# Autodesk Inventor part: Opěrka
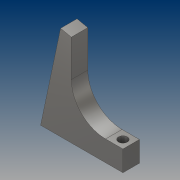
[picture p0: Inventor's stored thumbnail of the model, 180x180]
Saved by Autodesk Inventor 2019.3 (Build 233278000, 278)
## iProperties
Created: 2019-03
Part Number: Opěrka
Material: Ocel, litá
Document SubType Name: Modeling
Designer: B-hon
Density: 7.85 g/cm^3
Appearance: Pololeštěná
Author: B-hon
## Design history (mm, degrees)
sketch "Náčrt1"
  geometry: L1 (0, 0)-(14.554, 68.47); L2 (0, 0)-(70, 0); L3 (14.554, 68.47)-(22.379, 66.807); L4 (0, 0)-(60, 0); L5 (60, 0)-(60, 15); L6 (60, 15)-(47.379, 15); L7 (22.379, 40)-(22.379, 66.807); A1 r 25 centre (47.379, 40) between (22.379, 40) and (47.379, 15)
  constraints: 14 end point, 2 parallel, 2 point on circle, 2 tangent, 1 centre point, 1 equal length, 1 horizontal, 1 perpendicular, 1 point on line, 1 vertical
  dimensions: "d0" = 70 distance of L1.start L1.end; "d1" = 78 deg angle of L2 L1; "d2" = 8 distance of L1.end L3.end; "d3" = 15 distance of L4.end L5.end; "d4" = 60 distance from line of L1.start L5; "d5" = 25 radius of A1
extrude "Vysunutí1" new body sketch "Náčrt1" distance "d6" = 12; taper "d7" = 0 deg
sketch "Náčrt2"
  geometry: L1 (12.621, -12)-(0, -12) reference; L2 (12.621, 0)-(12.621, -12) reference; 2 further points
  dimensions: "d8" = 6 distance from line of L1 point (6.621, -6); "d9" = 6 distance from line of L2 point (6.621, -6)
hole "Díra1" sketch "Náčrt2" at (6.621, -6) diameter "d10" = 6.5; stored, may be unused: countersink angle "d14" = 90 deg, drill point angle "d16" = 118 deg; dims "d11" = 6, "d12" = 4, "d13" = 2, "d15" = 8
node "Těleso1"
